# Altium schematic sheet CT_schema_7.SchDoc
size 372 x 245 mm
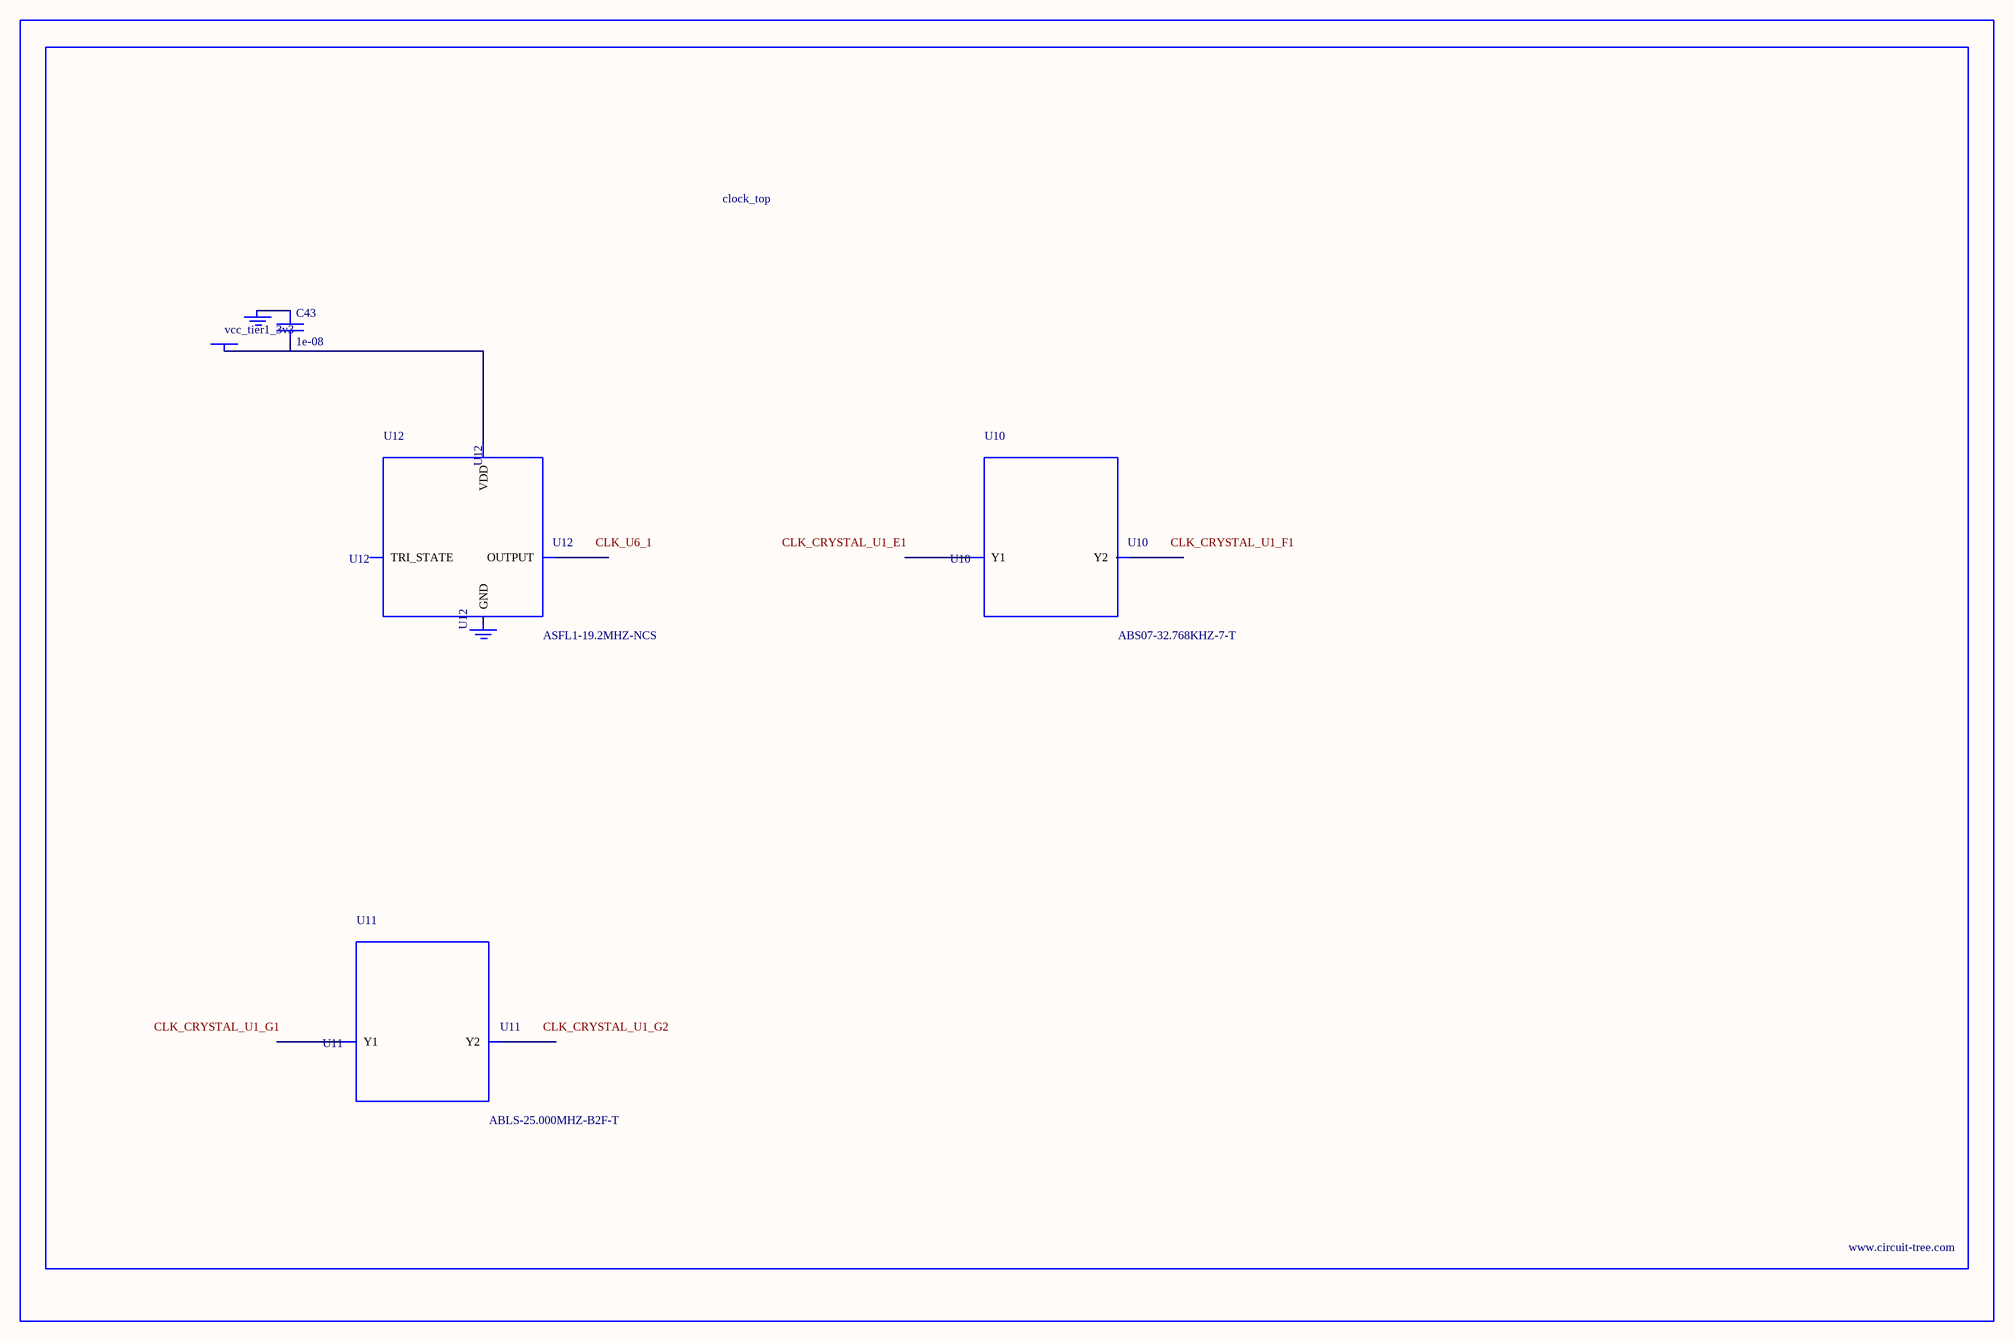
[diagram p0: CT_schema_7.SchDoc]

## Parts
BORDER6  (no value)
C43  1e-08  [C0402]
GND_INSTANCE_6_0  (no value)
GND_INSTANCE_6_1  (no value)
POWER_INSTANCE_6_0  vcc_tier1_3v3
U10  ABS07-32.768KHZ-7-T  [ABS07-32.768KHZ-7-T]
U11  ABLS-25.000MHZ-B2F-T  [ABLS-25.000MHZ-B2F-T]
U12  ASFL1-19.2MHZ-NCS  [ASFL1]

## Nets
NetC43_1: C43.1 GND_INSTANCE_6_0.0(GND)
NetC43_2: C43.2 POWER_INSTANCE_6_0.0(PWR) U12.4(VDD)

Not connected (* = marked no-connect by the designer): GND_INSTANCE_6_1 0(GND); U10 1(Y1) 2(Y2); U11 1(Y1) 2(Y2); U12 1(TRI_STATE) 2(GND) 3(OUTPUT)

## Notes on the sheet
- Labels drawn without touching a wire or pin: CLK_CRYSTAL_U1_E1, CLK_CRYSTAL_U1_F1, CLK_CRYSTAL_U1_G1, CLK_CRYSTAL_U1_G2, CLK_U6_1

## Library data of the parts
BORDER6 = BORDER_PAGE6
C43 = C0402C103K3RAC
GND_INSTANCE_6_0 GND_INSTANCE_6_1 = GND
POWER_INSTANCE_6_0 = PWR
